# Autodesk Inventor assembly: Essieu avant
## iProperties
Shininess: 41.0
Length Units: 11269
Angle Units: 11279
Time Units: 11290
Mass Units: 11283
Length Display Precision: 3
Angle Display Precision: 2
Compacted: True
Created: 2002-04
Part Number: Essieu avant
Document SubType Name: Assemblage
Designer: Flavien MARTY
Density: 0.0
Volumn: 0.0
Area: 0.0
PropertySet Name: Model Information
Control State: 0
Master: False
Checked Out: False
Author: Flavien MARTY
